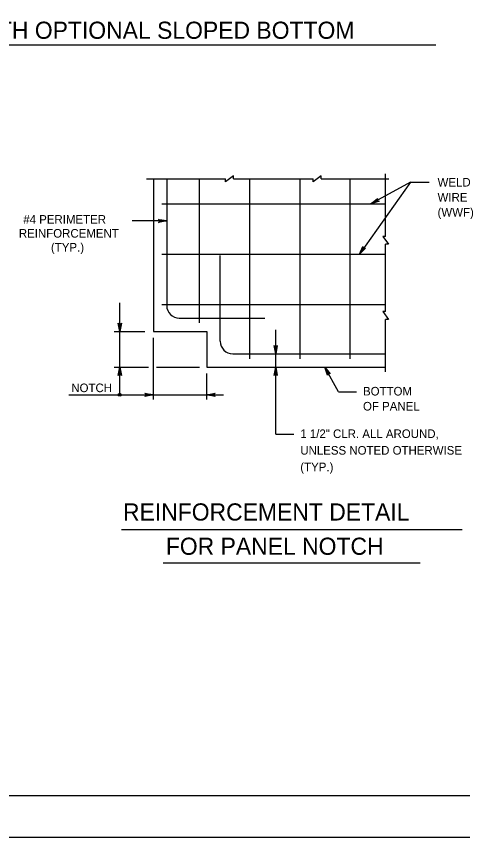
# Model space of a CAD drawing. Extents: x 3761 to 5458, y -616 to 1166.
# Drawn here: x 4936 to 5095.9, y -616.3 to -322.2 of the extents above; entities that cross this region are included whole.
import ezdxf

# ---------------------------------------------------------------- set-up
doc = ezdxf.new("R2010")
doc.units = 0
for name, color, linetype in [('1', 7, 'Continuous'), ('2', 7, 'Continuous'), ('PLT-BNDY', 7, 'Continuous')]:
    doc.layers.add(name, color=color, linetype=linetype)

msp = doc.modelspace()

# ---------------------------------------------------------------- linework, layer by layer
at = {"layer": '1'}
for p, q in [((4918.91, -332.44), (5086.33, -332.44)), ((5068.35, -401), (5068.35, -378.55)), ((4982.63, -380.41), (5010.98, -380.41)), ((4985.06, -380.41), (4985.06, -435.07)), ((4989.86, -380.41), (4989.86, -425.77)), ((5001.55, -380.41), (5001.55, -432)), ((5013.76, -380.41), (5042.4, -380.41)), ((5019.55, -380.41), (5019.55, -444.87)), ((5037.55, -380.41), (5037.55, -444.87)), ((5045.18, -380.41), (5069.52, -380.41)), ((5055.55, -380.41), (5055.55, -444.87)), ((5077.27, -381.6), (5058.92, -407.37)), ((5077.27, -381.6), (5063.09, -389.37)), ((5077.27, -381.6), (5084.01, -381.6)), ((4988.05, -389.37), (5068.35, -389.37)), ((4989.86, -395.48), (4977.42, -395.48)), ((5068.35, -427.95), (5068.35, -403.78)), ((4988.05, -407.37), (5068.35, -407.37)), ((5009.06, -438.57), (5009.06, -407.87)), ((4973.04, -457.74), (4973.04, -424.83)), ((4988.05, -425.37), (5068.35, -425.37)), ((4994.36, -430.27), (5025.06, -430.27)), ((5068.35, -449.5), (5068.35, -430.74)), ((4970.96, -435.07), (4982.05, -435.07)), ((4985.06, -435.07), (5004.26, -435.07)), ((5004.26, -435.07), (5004.26, -447.87)), ((5028.94, -471.87), (5028.94, -434.51)), ((4985.06, -459.36), (4985.06, -437.37)), ((5013.56, -443.07), (5068.35, -443.07)), ((4970.96, -447.87), (4983.28, -447.87)), ((4986.16, -447.87), (5001.56, -447.87)), ((5004.26, -447.87), (5068.35, -447.87)), ((5051.47, -456.66), (5046.54, -447.87)), ((5004.26, -459.36), (5004.26, -450.11)), ((4954.74, -457.74), (5010.18, -457.74)), ((5051.47, -456.66), (5057.89, -456.66)), ((5028.94, -471.87), (5035.41, -471.87)), ((4973.7, -505.96), (5095.74, -505.96)), ((4988.53, -517.96), (5080.73, -517.96))]:
    msp.add_line(p, q, dxfattribs=at)
for points in [[(5013.76, -380.41), (5013.76, -379.35), (5010.98, -381.47), (5010.98, -380.41)], [(5045.18, -380.41), (5045.18, -379.35), (5042.4, -381.47), (5042.4, -380.41)], [(5063.09, -389.37), (5065.43, -387.45), (5065.31, -387.7), (5065.3, -387.93), (5065.37, -388.12), (5065.49, -388.28), (5065.69, -388.4), (5065.97, -388.43), (5063.09, -389.37), (5065.69, -388.4), (5065.49, -388.28), (5063.09, -389.37), (5065.37, -388.12), (5065.3, -387.93), (5063.09, -389.37), (5065.31, -387.7)], [(4989.86, -395.48), (4986.87, -396.04), (4987.1, -395.88), (4987.22, -395.68), (4987.26, -395.48), (4987.22, -395.28), (4987.1, -395.08), (4986.87, -394.92), (4989.86, -395.48), (4987.1, -395.08), (4987.22, -395.28), (4989.86, -395.48), (4987.26, -395.48), (4987.22, -395.68), (4989.86, -395.48), (4987.1, -395.88)], [(5068.35, -400.99), (5067.29, -400.99), (5069.4, -403.78), (5068.35, -403.78)], [(5058.92, -407.37), (5060.2, -404.62), (5060.19, -404.9), (5060.29, -405.11), (5060.43, -405.25), (5060.61, -405.34), (5060.85, -405.36), (5061.11, -405.27), (5058.92, -407.37), (5060.85, -405.36), (5060.61, -405.34), (5058.92, -407.37), (5060.43, -405.25), (5060.29, -405.11), (5058.92, -407.37), (5060.19, -404.9)], [(5068.35, -427.95), (5067.29, -427.95), (5069.4, -430.74), (5068.35, -430.74)], [(4973.04, -435.07), (4972.48, -432.09), (4972.64, -432.32), (4972.84, -432.44), (4973.04, -432.47), (4973.24, -432.44), (4973.44, -432.32), (4973.6, -432.09), (4973.04, -435.07), (4973.44, -432.32), (4973.24, -432.44), (4973.04, -435.07), (4973.04, -432.47), (4972.84, -432.44), (4973.04, -435.07), (4972.64, -432.32)], [(5028.94, -443.07), (5028.38, -440.09), (5028.54, -440.32), (5028.74, -440.44), (5028.94, -440.47), (5029.14, -440.44), (5029.34, -440.32), (5029.5, -440.09), (5028.94, -443.07), (5029.34, -440.32), (5029.14, -440.44), (5028.94, -443.07), (5028.94, -440.47), (5028.74, -440.44), (5028.94, -443.07), (5028.54, -440.32)], [(4973.04, -447.87), (4973.6, -450.85), (4973.44, -450.62), (4973.24, -450.51), (4973.04, -450.47), (4972.84, -450.51), (4972.64, -450.62), (4972.48, -450.85), (4973.04, -447.87), (4972.64, -450.62), (4972.84, -450.51), (4973.04, -447.87), (4973.04, -450.47), (4973.24, -450.51), (4973.04, -447.87), (4973.44, -450.62)], [(5028.94, -447.87), (5029.5, -450.85), (5029.34, -450.62), (5029.14, -450.51), (5028.94, -450.47), (5028.74, -450.51), (5028.54, -450.62), (5028.38, -450.85), (5028.94, -447.87), (5028.54, -450.62), (5028.74, -450.51), (5028.94, -447.87), (5028.94, -450.47), (5029.14, -450.51), (5028.94, -447.87), (5029.34, -450.62)], [(5046.54, -447.87), (5048.49, -450.2), (5048.24, -450.08), (5048.01, -450.07), (5047.82, -450.14), (5047.66, -450.27), (5047.54, -450.47), (5047.52, -450.75), (5046.54, -447.87), (5047.54, -450.47), (5047.66, -450.27), (5046.54, -447.87), (5047.82, -450.14), (5048.01, -450.07), (5046.54, -447.87), (5048.24, -450.08)], [(4985.06, -457.74), (4982.07, -458.29), (4982.3, -458.14), (4982.42, -457.94), (4982.46, -457.74), (4982.42, -457.54), (4982.3, -457.34), (4982.07, -457.18), (4985.06, -457.74), (4982.3, -457.34), (4982.42, -457.54), (4985.06, -457.74), (4982.46, -457.74), (4982.42, -457.94), (4985.06, -457.74), (4982.3, -458.14)], [(5004.26, -457.74), (5007.24, -457.18), (5007.01, -457.34), (5006.89, -457.54), (5006.86, -457.74), (5006.89, -457.94), (5007.01, -458.14), (5007.24, -458.29), (5004.26, -457.74), (5007.01, -458.14), (5006.89, -457.94), (5004.26, -457.74), (5006.86, -457.74), (5006.89, -457.54), (5004.26, -457.74), (5007.01, -457.34)]]:
    msp.add_lwpolyline(points, dxfattribs=at)
for radius in [0.533, 0.267]:
    msp.add_circle((4973.04, -457.74), radius, dxfattribs=at)
for centre in [(4994.36, -425.77), (5013.56, -438.57)]:
    msp.add_arc(centre, 4.5, 180, 270, dxfattribs=at)
at = {"layer": '2'}
msp.add_line((5428.34, -601.31), (4642.34, -601.31), dxfattribs=at)
at = {"layer": 'PLT-BNDY'}
msp.add_lwpolyline([(4602.34, -22.31), (5443.34, -22.31), (5443.34, -616.31), (4602.34, -616.31)], close=True, dxfattribs=at)

# ---------------------------------------------------------------- texts
at = {"layer": '1'}
for s, height, p in [('WITH OPTIONAL SLOPED BOTTOM', 6.144, (4919.3, -330.24)), ('WELDED', 3.072, (5086.96, -383.14)), ('WIRE FABRIC', 3.072, (5086.96, -388.52)), ('(WWF)', 3.072, (5086.96, -393.89)), ('#4 PERIMETER', 3.072, (4938.43, -396.45)), ('REINFORCEMENT', 3.072, (4936.84, -401.44)), ('(TYP.) ', 3.072, (4948.36, -406.43)), ('NOTCH', 3.072, (4955.65, -456.78)), ('BOTTOM', 3.072, (5060.23, -457.98)), ('OF PANEL', 3.072, (5060.23, -463.36)), ('1 1/2" CLR. ALL AROUND,', 3.072, (5037.75, -473.21)), ('UNLESS NOTED OTHERWISE', 3.072, (5037.75, -479.16)), ('(TYP.)', 3.072, (5037.75, -485.11)), ('REINFORCEMENT DETAIL', 6.144, (4974.18, -502.76)), ('FOR PANEL NOTCH', 6.144, (4989.54, -515.04))]:
    msp.add_text(s, height=height, dxfattribs=at).set_placement(p)

doc.saveas('drawing.dxf')
